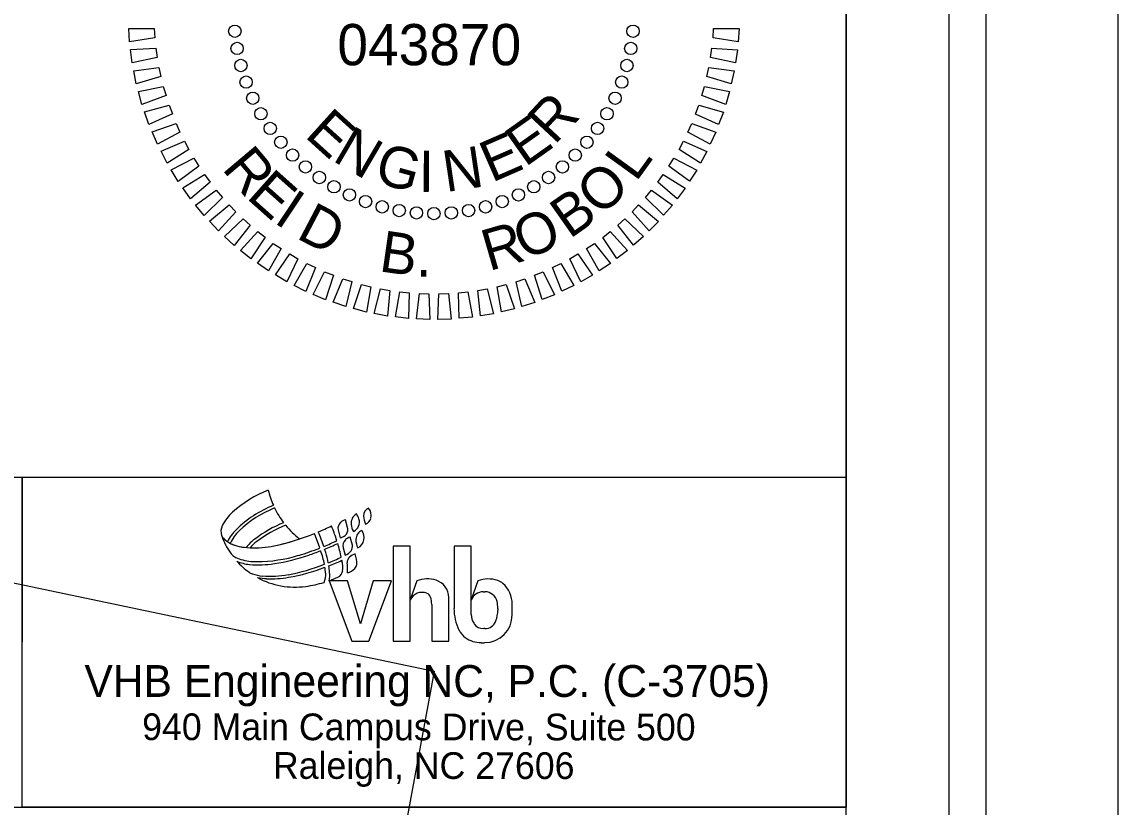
# Model space of a CAD drawing. Extents: x 1633303 to 1635397, y 883210 to 885302.
# Drawn here: x 1635263.8 to 1635396.9, y 884795.1 to 884890.3 of the extents above; entities that cross this region are included whole.
import ezdxf

# ---------------------------------------------------------------- set-up
doc = ezdxf.new("R2010")
doc.units = 0
for name, color, linetype in [('Default', 7, 'Continuous'), ('Scratch_Level_8', 7, 'Continuous'), ('Sheet PE Seal Cell', 7, 'Continuous'), ('Sheet Plan And Profile CELL', 7, 'Continuous'), ('Sheet Plot Border Inside CELL', 7, 'Continuous'), ('Sheet Plot Border Outside CELL', 7, 'Continuous'), ('Sheet Profile CELL', 7, 'Continuous'), ('Stewart Plot Border Xerox6279 and LJ5000', 7, 'Continuous')]:
    doc.layers.add(name, color=color, linetype=linetype)

msp = doc.modelspace()

# ---------------------------------------------------------------- linework, layer by layer
at = {"layer": 'Default'}
for p, q in [((1635303.41, 884828.8), (1635303.1, 884829.91)), ((1635302.2, 884828.69), (1635302.48, 884827.71)), ((1635299.98, 884826.49), (1635299.35, 884828.25)), ((1635303.95, 884826.84), (1635303.68, 884827.81)), ((1635302.81, 884826.51), (1635303.06, 884825.61)), ((1635310.96, 884826.72), (1635308.88, 884826.72)), ((1635308.88, 884826.72), (1635308.88, 884815.19)), ((1635318.36, 884826.72), (1635316.28, 884826.72)), ((1635316.28, 884826.72), (1635316.28, 884819.16)), ((1635301.13, 884822.49), (1635302.19, 884822.96)), ((1635303.35, 884822.49), (1635301.13, 884822.49)), ((1635301.13, 884822.49), (1635303.87, 884815.19)), ((1635304.91, 884817.28), (1635303.35, 884822.49)), ((1635306.48, 884822.49), (1635304.91, 884817.28)), ((1635305.96, 884815.19), (1635308.7, 884822.49)), ((1635308.7, 884822.49), (1635306.48, 884822.49)), ((1635311.77, 884822.49), (1635310.96, 884820.18)), ((1635319.17, 884822.49), (1635318.36, 884820.18)), ((1635315.65, 884815.19), (1635315.65, 884820.48)), ((1635319.83, 884821.17), (1635320.02, 884821.17)), ((1635313.57, 884819.65), (1635313.57, 884815.19)), ((1635321.59, 884819.16), (1635321.59, 884818.94)), ((1635323.34, 884818.36), (1635323.34, 884819.67)), ((1635320.01, 884816.71), (1635319.88, 884816.71)), ((1635303.87, 884815.19), (1635305.96, 884815.19)), ((1635308.88, 884815.19), (1635310.96, 884815.19)), ((1635313.57, 884815.19), (1635315.65, 884815.19)), ((1635319.57, 884814.99), (1635319.98, 884814.99)), ((1635163.83, 884795.06), (1635363.86, 884795.06)), ((1635163.83, 884795.06), (1635363.86, 884795.06))]:
    msp.add_line(p, q, dxfattribs=at)
msp.add_lwpolyline([(1635263.86, 884835.06), (1635363.86, 884835.06), (1635363.86, 884795.06), (1635263.86, 884795.06)], close=True, dxfattribs=at)
for points in [[(1635310.96, 884815.19), (1635310.96, 884820.18), (1635310.96, 884826.72)], [(1635318.36, 884818.41), (1635318.36, 884820.18), (1635318.36, 884826.72)]]:
    msp.add_lwpolyline(points, dxfattribs=at)
for centre, major_axis, start_param, end_param in [((1635299.05, 884820.18), (14.36, 0), 1.950459, 2.306295), ((1635304.02, 884835.96), (10.58, 0), 3.374816, 3.559712), ((1635299.61, 884818.71), (13.98, 0), 1.955908, 2.345415), ((1635299.61, 884818.71), (13.63, 0), 1.954608, 2.331375), ((1635304.02, 884835.96), (10.58, 0), 3.593328, 3.791245), ((1635306.28, 884830.41), (0.982, 0), 1.950799, 3.19085), ((1635304.87, 884830.46), (1.36, 0), 6.010502, 6.978239), ((1635293.32, 884826.52), (5.82, 0), 2.306295, 2.663056), ((1635303.4, 884828.66), (1.28, 0), 1.805558, 2.340862), ((1635305.07, 884829.51), (1.28, 0), 2.069357, 3.26373), ((1635303.52, 884829.64), (1.28, 0), 5.158115, 6.583255), ((1635302.36, 884829.28), (2.49, 0), 0.300085, 0.573578), ((1635307.79, 884830.49), (2.49, 0), 3.190836, 3.597778), ((1635305.16, 884830.37), (1.06, 0), 5.088672, 6.010509), ((1635289.5, 884828.5), (1.51, 0), 2.663056, 3.487291), ((1635293.53, 884824.92), (5.29, 0), 2.345415, 2.685879), ((1635293.6, 884825.03), (4.91, 0), 2.331375, 2.717794), ((1635301.29, 884815.56), (15.11, 0), 1.956929, 2.223843), ((1635301.29, 884815.56), (14.73, 0), 1.949325, 2.223843), ((1635304.02, 884835.96), (10.58, 0), 3.829221, 4.05458), ((1635288.1, 884856.3), (30.23, 0), 5.110242, 5.168312), ((1635264.71, 884814.43), (37.79, 0), 0.330018, 0.379866), ((1635264.71, 884814.43), (39.54, 0), 0.355324, 0.381952), ((1635303.21, 884828.85), (1.02, 0), 2.340862, 3.293303), ((1635302.39, 884828.77), (1.02, 0), 5.445151, 6.311085), ((1635306.27, 884829.66), (2.49, 0), 3.26373, 3.631752), ((1635305.58, 884827.5), (1.21, 0), 1.982585, 3.114577), ((1635303.78, 884827.72), (1.59, 0), 6.124862, 6.873863), ((1635296.96, 884831.19), (9.45, 0), 3.487291, 3.49224), ((1635288.8, 884828.2), (0.756, 0), 3.492238, 3.942132), ((1635288.8, 884828.2), (0.756, 0), 3.492238, 3.942132), ((1635296.96, 884831.19), (9.45, 0), 3.492238, 3.737263), ((1635290.86, 884830.32), (3.7, 0), 3.942115, 4.117328), ((1635290.86, 884830.32), (3.7, 0), 3.942115, 4.535322), ((1635290.86, 884830.32), (3.7, 0), 4.225969, 4.535322), ((1635296.24, 884822.17), (6.8, 0), 2.223843, 2.440018), ((1635296.24, 884822.17), (6.42, 0), 2.223843, 2.396036), ((1635288.1, 884856.3), (30.23, 0), 4.923489, 5.093727), ((1635288.1, 884856.3), (30.23, 0), 4.923489, 5.030725), ((1635288.1, 884856.3), (32.11, 0), 5.107726, 5.162272), ((1635288.1, 884856.3), (32.47, 0), 5.106941, 5.160619), ((1635283.51, 884821.4), (19.49, 0), 0.312292, 0.355324), ((1635283.51, 884821.4), (19.49, 0), 0.205325, 0.293478), ((1635302.21, 884828.97), (1.28, 0), 4.922279, 5.445148), ((1635303.76, 884826.76), (0.982, 0), 2.294387, 3.400315), ((1635304.06, 884826.42), (1.44, 0), 1.838184, 2.294391), ((1635306.49, 884827.47), (2.12, 0), 3.114567, 3.617561), ((1635304.08, 884827.68), (1.28, 0), 5.137017, 6.124854), ((1635290.4, 884826.74), (1.51, 0), 3.737263, 4.155114), ((1635292.13, 884837.46), (10.96, 0), 4.535322, 4.613027), ((1635292.13, 884837.46), (10.96, 0), 4.535322, 4.657076), ((1635292.13, 884837.46), (10.96, 0), 4.657076, 4.923489), ((1635292.13, 884837.46), (10.96, 0), 4.657076, 4.923489), ((1635290.78, 884848.49), (24.18, 0), 4.866042, 5.043468), ((1635288.1, 884856.3), (32.1, 0), 5.007435, 5.091777), ((1635288.1, 884856.3), (32.44, 0), 5.043468, 5.091439), ((1635290.15, 884822.56), (10.58, 0), 0.186675, 0.34709), ((1635264.71, 884814.43), (37.79, 0), 0.309699, 0.320394), ((1635290.15, 884822.56), (11.08, 0), 0.192744, 0.309699), ((1635302.61, 884826.98), (1.44, 0), 5.034707, 5.66976), ((1635304.99, 884823.78), (2.12, 0), 1.905419, 2.288613), ((1635302.98, 884826.72), (0.982, 0), 5.669754, 6.410867), ((1635300.79, 884824.57), (3.7, 0), 6.258511, 6.615609), ((1635291.28, 884828.15), (3.17, 0), 4.155114, 4.433304), ((1635291.87, 884829.16), (4.69, 0), 4.281835, 4.626581), ((1635296.96, 884831.19), (9.45, 0), 3.869789, 4.084312), ((1635292.32, 884831.78), (6.95, 0), 4.433304, 4.717272), ((1635292.55, 884837.06), (12.62, 0), 4.626581, 4.866042), ((1635292.26, 884842.59), (17.76, 0), 4.717272, 5.007435), ((1635292.02, 884845.53), (22.67, 0), 4.896065, 5.098239), ((1635288.1, 884856.3), (34.16, 0), 5.100586, 5.150688), ((1635288.1, 884856.3), (34.53, 0), 5.098273, 5.148033), ((1635290.15, 884822.56), (11.08, 0), 0.08898, 0.158557), ((1635283.51, 884821.4), (19.49, 0), 0.162521, 0.185756), ((1635299.76, 884824.06), (3.02, 0), 6.17953, 6.445706), ((1635304.14, 884824.75), (0.831, 0), 2.288613, 3.208516), ((1635297.09, 884823.88), (6.27, 0), 6.218327, 6.411973), ((1635303.67, 884824.6), (0.831, 0), 5.49053, 6.137671), ((1635292.3, 884824.77), (1.51, 0), 4.084312, 4.375641), ((1635293.43, 884827.98), (4.91, 0), 4.375641, 4.631331), ((1635293.99, 884834.91), (11.86, 0), 4.631331, 4.896065), ((1635292.7, 884843.8), (21.16, 0), 4.878361, 5.095384), ((1635298.44, 884823.24), (2.27, 0), 5.862276, 6.364042), ((1635290.15, 884822.56), (10.58, 0), 0.080866, 0.152313), ((1635297.42, 884823.21), (3.78, 0), 6.089473, 6.37216), ((1635301.79, 884823.85), (0.982, 0), 5.129856, 6.17953), ((1635302.77, 884825.51), (2.12, 0), 4.991009, 5.49053), ((1635293.83, 884829.71), (6.95, 0), 4.511808, 4.670453), ((1635296.96, 884831.19), (9.45, 0), 4.213149, 4.853258), ((1635294.07, 884835.6), (12.85, 0), 4.670453, 4.878361), ((1635296.01, 884837.92), (16.25, 0), 4.853258, 4.99278), ((1635313.07, 884819.22), (3.51, 0), 1.271815, 1.948427), ((1635313.45, 884820.48), (2.19, 0), 6.283185, 7.555001), ((1635320.46, 884819.22), (3.51, 0), 1.243417, 1.948427), ((1635321.01, 884820.83), (1.81, 0), 0.841181, 1.243417), ((1635319.98, 884819.67), (3.36, 0), 0, 0.841181), ((1635312.4, 884819.51), (-1.59, 0), 4.330931, 5.84316), ((1635312.71, 884820.28), (-0.756, 0), 3.478495, 4.330931), ((1635310.92, 884819.65), (2.65, 0), 0, 0.336903), ((1635319.83, 884819.58), (1.59, 0), 1.570796, 2.75299), ((1635320.02, 884819.66), (1.51, 0), 0.218399, 1.570796), ((1635322.32, 884819.16), (-6.05, 0), 0, 0.452165), ((1635317.81, 884819.16), (3.78, 0), 6.283185, 6.501584), ((1635320.25, 884818.41), (-1.89, 0), 6.283185, 6.906012), ((1635319.98, 884818.36), (3.36, 0), 4.712389, 6.283185), ((1635320.01, 884818.14), (1.44, 0), 4.712389, 5.93764), ((1635317.81, 884818.94), (3.78, 0), 5.93764, 6.283185), ((1635319.06, 884817.58), (-2.42, 0), 0.452165, 0.946963), ((1635319.88, 884818.14), (-1.44, 0), 0.622827, 1.570796), ((1635319.57, 884818.29), (-3.29, 0), 0.946963, 1.570796)]:
    msp.add_ellipse(centre, major_axis=major_axis, ratio=0.999914, start_param=start_param, end_param=end_param, dxfattribs=at)
at = {"layer": 'Scratch_Level_8'}
msp.add_lwpolyline([(1634013.86, 883947.61), (1634013.86, 885084.12), (1635313.86, 884811.56), (1635263.86, 884541.53), (1635263.86, 883947.61)], close=True, dxfattribs=at)
at = {"layer": 'Sheet PE Seal Cell'}
for points in [[(1635279.97, 884888.37), (1635276.89, 884887.92), (1635276.8, 884889.53), (1635279.89, 884889.51)], [(1635347.78, 884889.51), (1635350.9, 884889.52), (1635350.76, 884887.91), (1635347.71, 884888.37)], [(1635280.26, 884886.01), (1635277.21, 884885.35), (1635277.02, 884886.95), (1635280.1, 884887.14)], [(1635347.57, 884887.14), (1635350.69, 884886.94), (1635350.43, 884885.35), (1635347.42, 884886.01)], [(1635280.71, 884883.68), (1635277.72, 884882.81), (1635277.41, 884884.39), (1635280.47, 884884.8)], [(1635347.2, 884884.8), (1635350.29, 884884.38), (1635349.93, 884882.81), (1635346.97, 884883.68)], [(1635281.33, 884881.39), (1635278.4, 884880.31), (1635277.98, 884881.87), (1635281, 884882.49)], [(1635346.66, 884882.49), (1635349.72, 884881.86), (1635349.25, 884880.31), (1635346.36, 884881.39)], [(1635282.1, 884879.15), (1635279.25, 884877.86), (1635278.73, 884879.39), (1635281.7, 884880.22)], [(1635345.97, 884880.22), (1635348.97, 884879.38), (1635348.39, 884877.87), (1635345.59, 884879.14)], [(1635283.02, 884876.96), (1635280.28, 884875.48), (1635279.65, 884876.97), (1635282.55, 884878)], [(1635345.12, 884878.01), (1635348.06, 884876.96), (1635347.37, 884875.49), (1635344.66, 884876.96)], [(1635284.1, 884874.85), (1635281.46, 884873.18), (1635280.73, 884874.62), (1635283.56, 884875.85)], [(1635344.11, 884875.86), (1635346.97, 884874.6), (1635346.19, 884873.19), (1635343.58, 884874.84)], [(1635285.32, 884872.81), (1635282.81, 884870.96), (1635281.97, 884872.35), (1635284.71, 884873.78)], [(1635342.96, 884873.78), (1635345.73, 884872.33), (1635344.85, 884870.98), (1635342.36, 884872.81)], [(1635286.68, 884870.87), (1635284.3, 884868.85), (1635283.37, 884870.17), (1635286, 884871.79)], [(1635341.67, 884871.79), (1635344.33, 884870.16), (1635343.35, 884868.86), (1635341, 884870.86)], [(1635288.17, 884869.03), (1635285.94, 884866.84), (1635284.92, 884868.1), (1635287.43, 884869.9)], [(1635340.24, 884869.9), (1635342.78, 884868.08), (1635341.71, 884866.86), (1635339.51, 884869.02)], [(1635289.79, 884867.29), (1635287.71, 884864.96), (1635286.61, 884866.14), (1635288.99, 884868.11)], [(1635338.68, 884868.11), (1635341.08, 884866.12), (1635339.94, 884864.98), (1635337.89, 884867.28)], [(1635291.52, 884865.67), (1635289.61, 884863.2), (1635288.43, 884864.3), (1635290.67, 884866.43)], [(1635337, 884866.43), (1635339.26, 884864.28), (1635338.04, 884863.22), (1635336.16, 884865.66)], [(1635293.36, 884864.18), (1635291.63, 884861.58), (1635290.38, 884862.6), (1635292.46, 884864.87)], [(1635335.21, 884864.88), (1635337.31, 884862.57), (1635336.02, 884861.6), (1635334.32, 884864.17)], [(1635295.31, 884862.81), (1635293.76, 884860.1), (1635292.44, 884861.03), (1635294.35, 884863.45)], [(1635333.32, 884863.45), (1635335.25, 884861), (1635333.9, 884860.12), (1635332.37, 884862.81)], [(1635297.34, 884861.59), (1635295.99, 884858.78), (1635294.6, 884859.61), (1635296.35, 884862.16)], [(1635331.32, 884862.16), (1635333.09, 884859.58), (1635331.67, 884858.8), (1635330.34, 884861.58)], [(1635299.45, 884860.51), (1635298.3, 884857.61), (1635296.86, 884858.35), (1635298.42, 884861.01)], [(1635329.25, 884861.01), (1635330.83, 884858.32), (1635329.36, 884857.64), (1635328.23, 884860.5)], [(1635301.64, 884859.58), (1635300.69, 884856.61), (1635299.2, 884857.24), (1635300.57, 884860)], [(1635303.88, 884858.81), (1635303.14, 884855.78), (1635301.61, 884856.3), (1635302.79, 884859.16)], [(1635324.88, 884859.16), (1635326.07, 884856.28), (1635324.52, 884855.8), (1635323.8, 884858.8)], [(1635327.1, 884860.01), (1635328.48, 884857.21), (1635326.97, 884856.64), (1635326.04, 884859.58)], [(1635306.17, 884858.19), (1635305.65, 884855.12), (1635304.09, 884855.54), (1635305.06, 884858.46)], [(1635308.5, 884857.74), (1635308.19, 884854.63), (1635306.6, 884854.94), (1635307.37, 884857.93)], [(1635310.85, 884857.45), (1635310.76, 884854.33), (1635309.16, 884854.53), (1635309.72, 884857.56)], [(1635317.96, 884857.57), (1635318.52, 884854.5), (1635316.91, 884854.36), (1635316.82, 884857.44)], [(1635320.3, 884857.94), (1635321.07, 884854.91), (1635319.48, 884854.66), (1635319.18, 884857.73)], [(1635322.61, 884858.47), (1635323.6, 884855.51), (1635322.02, 884855.14), (1635321.51, 884858.19)], [(1635313.22, 884857.32), (1635313.35, 884854.2), (1635311.74, 884854.29), (1635312.08, 884857.36)], [(1635315.59, 884857.36), (1635315.94, 884854.26), (1635314.32, 884854.23), (1635314.45, 884857.32)]]:
    msp.add_lwpolyline(points, close=True, dxfattribs=at)
for centre in [(1635289.68, 884889.19), (1635338, 884889.19), (1635289.96, 884887.1), (1635337.72, 884887.1), (1635290.41, 884885.03), (1635337.26, 884885.03), (1635291.05, 884883.01), (1635336.63, 884883.01), (1635291.86, 884881.06), (1635335.82, 884881.06), (1635292.84, 884879.18), (1635334.84, 884879.18), (1635293.97, 884877.4), (1635333.7, 884877.4), (1635295.26, 884875.72), (1635332.41, 884875.72), (1635296.69, 884874.16), (1635330.99, 884874.16), (1635298.25, 884872.73), (1635299.93, 884871.44), (1635327.75, 884871.44), (1635329.43, 884872.73), (1635301.71, 884870.31), (1635325.96, 884870.31), (1635303.59, 884869.33), (1635324.09, 884869.33), (1635305.54, 884868.52), (1635307.56, 884867.88), (1635309.63, 884867.43), (1635318.05, 884867.43), (1635320.11, 884867.88), (1635322.13, 884868.52), (1635311.72, 884867.15), (1635313.84, 884867.06), (1635315.95, 884867.15)]:
    msp.add_circle(centre, 0.75, dxfattribs=at)
at = {"layer": 'Sheet Plan And Profile CELL'}
for p, q in [((1635263.86, 884835.06), (1635263.84, 884795.06)), ((1635163.83, 884795.06), (1635363.86, 884795.06))]:
    msp.add_line(p, q, dxfattribs=at)
at = {"layer": 'Sheet Plot Border Inside CELL'}
msp.add_lwpolyline([(1635376.36, 884975.16), (1633709.86, 884975.16), (1633709.86, 883920.06), (1635376.36, 883920.06)], close=True, dxfattribs=at)
at = {"layer": 'Sheet Plot Border Outside CELL'}
msp.add_lwpolyline([(1635380.86, 884997.61), (1633696.86, 884997.61), (1633696.86, 883897.61), (1635380.86, 883897.61)], close=True, dxfattribs=at)
at = {"layer": 'Sheet Profile CELL'}
msp.add_line((1635363.86, 884947.56), (1635363.86, 884835.06), dxfattribs=at)
msp.add_lwpolyline([(1635363.86, 884972.61), (1633863.86, 884972.61), (1633863.86, 883922.61), (1635363.86, 883922.61)], close=True, dxfattribs=at)
msp.add_lwpolyline([(1635163.81, 884947.56), (1635163.81, 884835.06), (1635363.86, 884835.06)], dxfattribs=at)
at = {"layer": 'Stewart Plot Border Xerox6279 and LJ5000'}
msp.add_lwpolyline([(1633696.86, 883897.61), (1635396.86, 883897.61), (1635396.86, 884997.61), (1633696.86, 884997.61)], close=True, dxfattribs=at)

# ---------------------------------------------------------------- texts
at = {"layer": 'Default'}
for s, height, rotation, p in [('VHB Engineering NC, P.C. (C-3705)', 3.8596, 360, (1635271.43, 884808.42)), ('940 Main Campus Drive, Suite 500', 3.2388, 359.9612, (1635278.43, 884803.18)), ('Raleigh, NC 27606', 3.2388, 359.9612, (1635294.3, 884798.48))]:
    msp.add_text(s, height=height, rotation=rotation, dxfattribs=at).set_placement(p)
at = {"layer": 'Sheet PE Seal Cell'}
msp.add_text('043870', height=5, dxfattribs=at).set_placement((1635302.12, 884885.06))
for s, rotation, p in [('R', 47.043, (1635328.47, 884875.29)), ('E', 317.8506, (1635298.03, 884876.45)), ('E', 35.2807, (1635324.9, 884872.64)), ('N', 329.6129, (1635301.39, 884873.54)), ('E', 23.5185, (1635320.86, 884870.78)), ('R', 310.1625, (1635288.01, 884872.49)), ('G', 344.6629, (1635306.43, 884870.92)), ('N', 8.4684, (1635315.29, 884869.66)), ('I', 359.713, (1635311.98, 884869.69)), ('L', 54.176, (1635338.35, 884870.8)), ('E', 318.3712, (1635290.96, 884869)), ('O', 43.4508, (1635334.1, 884866.6)), ('I', 326.3511, (1635294.28, 884866.04)), ('B', 35.1087, (1635330.3, 884863.92)), ('D', 332.291, (1635297, 884864.15)), ('O', 24.3836, (1635324.92, 884861.33)), ('R', 16.1749, (1635320.52, 884860.06)), ('B', 351.8635, (1635307.07, 884860.08)), ('.', 0.2056, (1635311.67, 884859.42))]:
    msp.add_text(s, height=5, rotation=rotation, dxfattribs=at).set_placement(p)

doc.saveas('drawing.dxf')
